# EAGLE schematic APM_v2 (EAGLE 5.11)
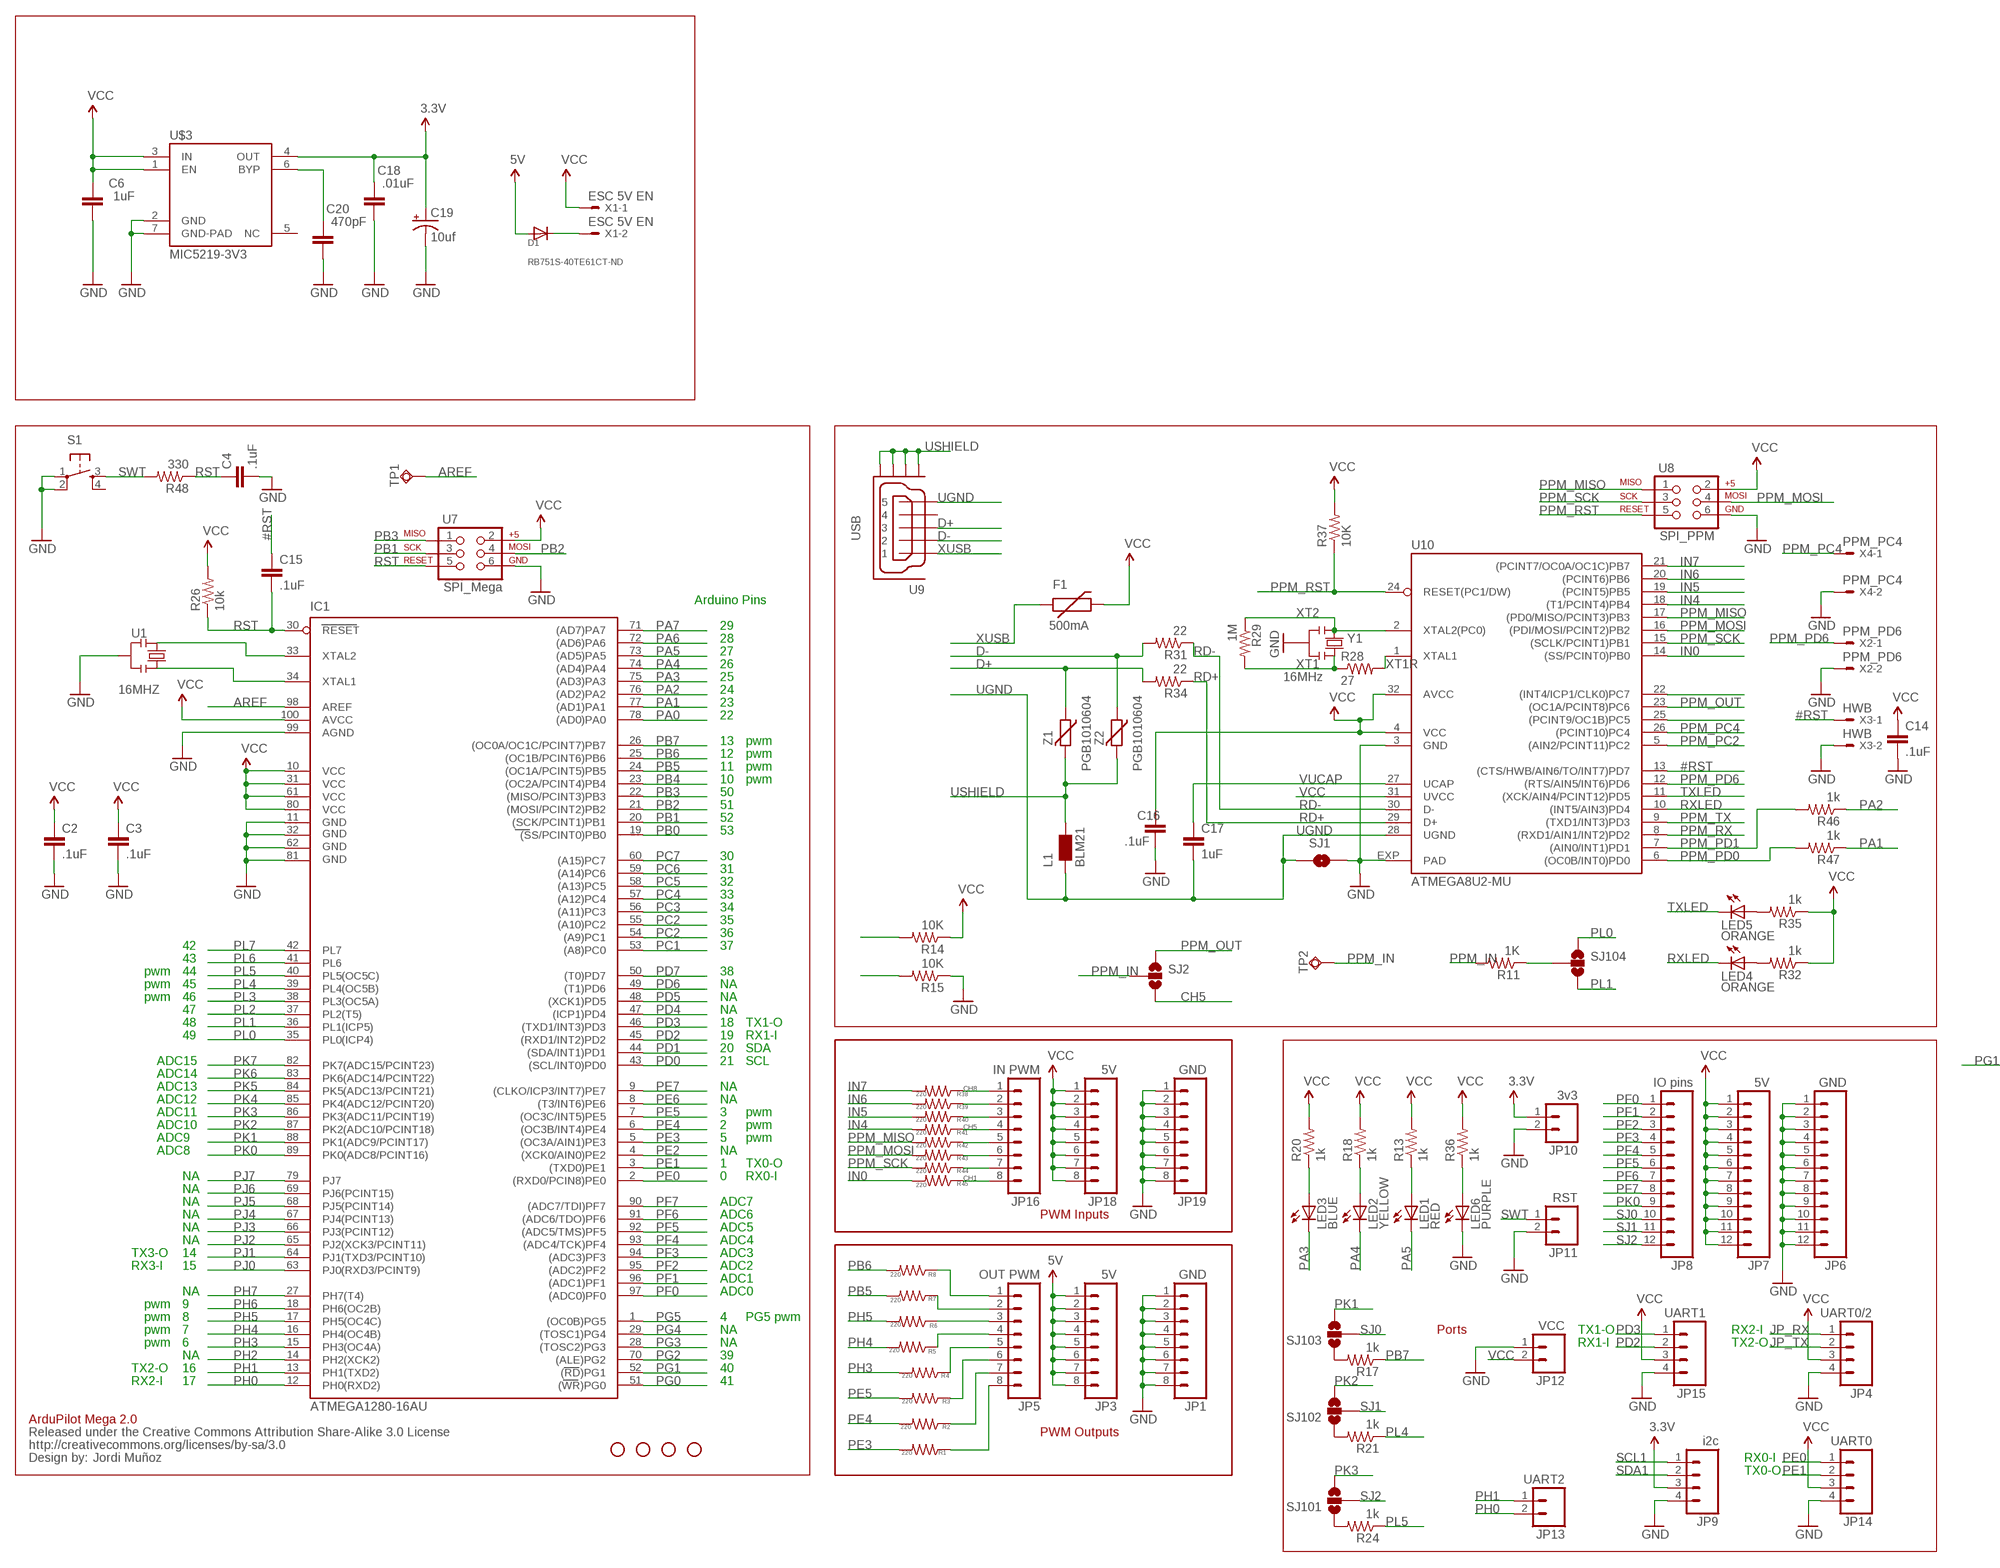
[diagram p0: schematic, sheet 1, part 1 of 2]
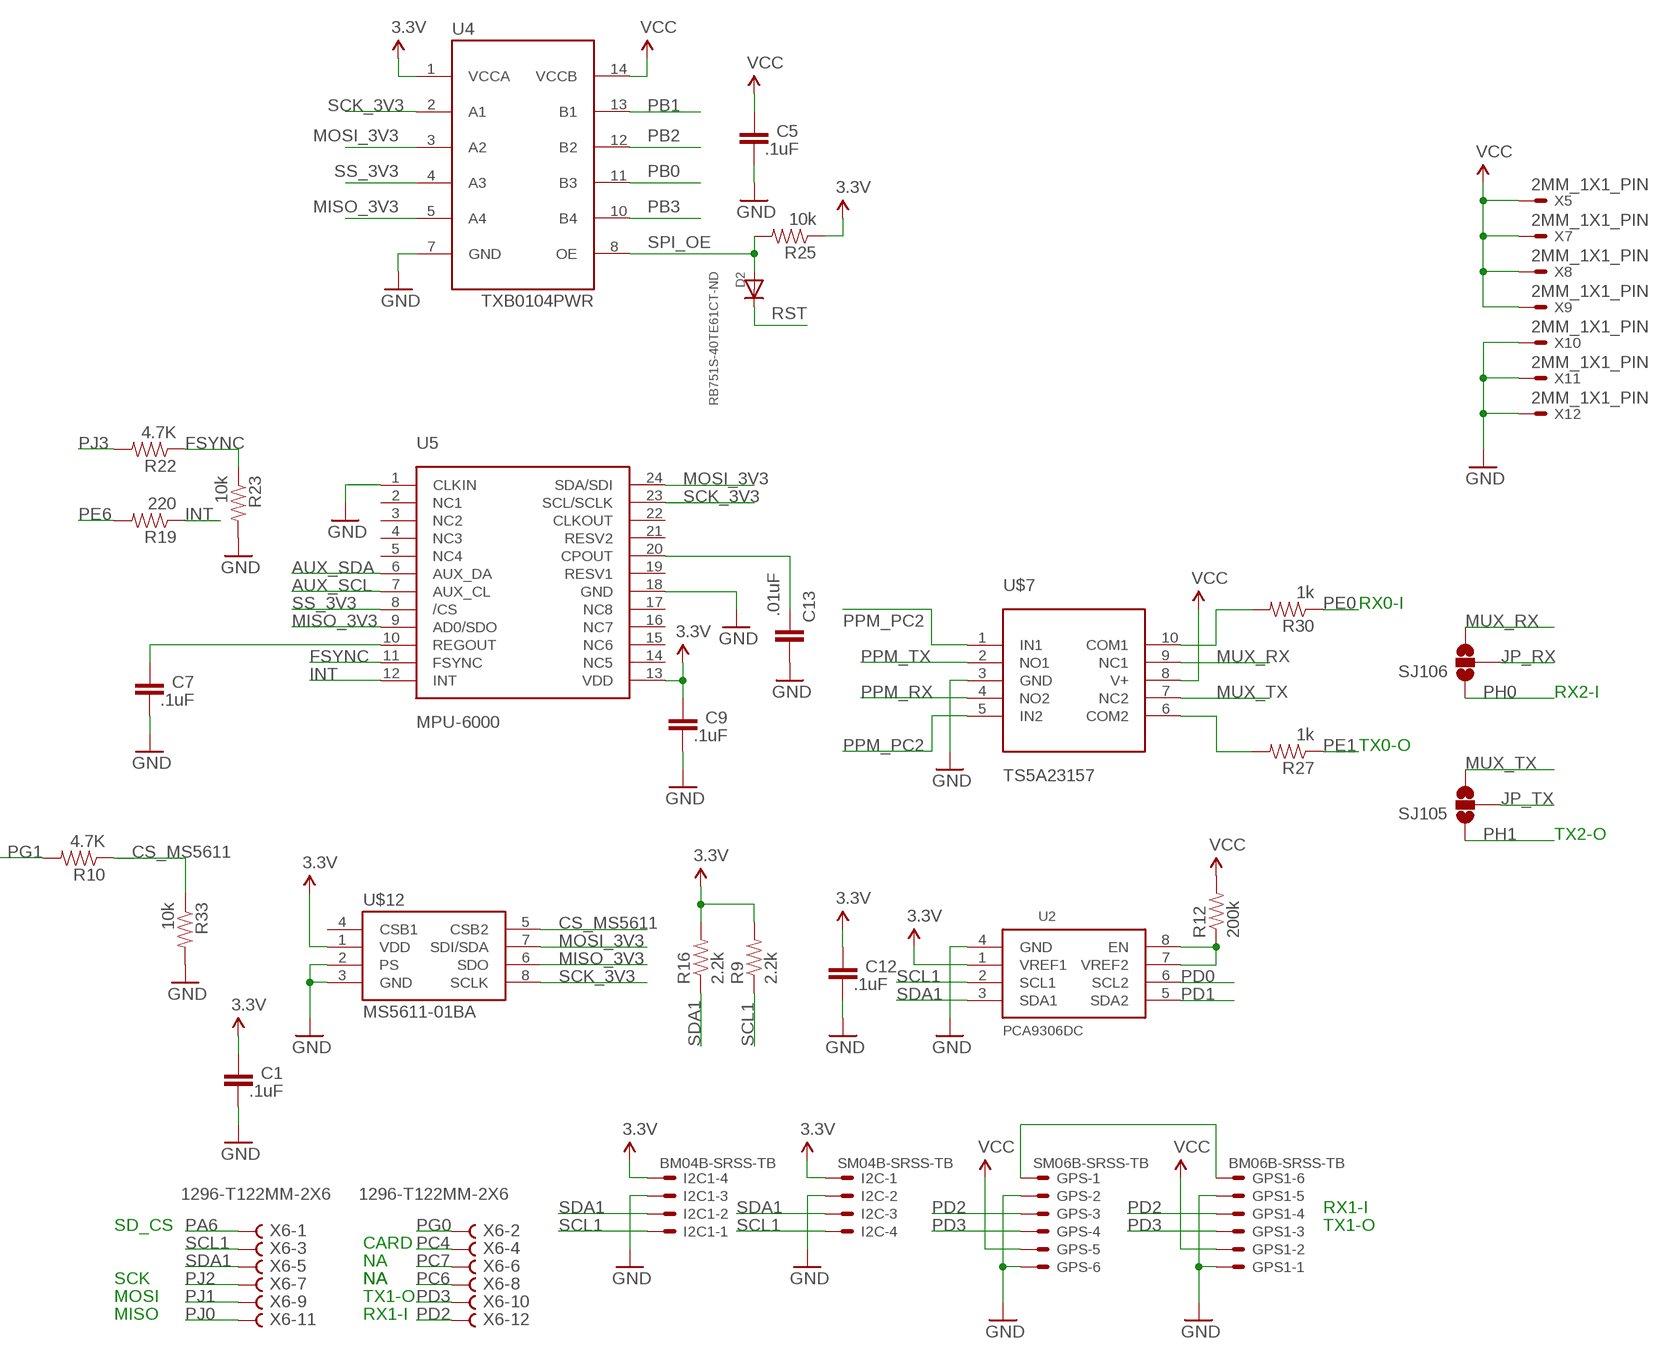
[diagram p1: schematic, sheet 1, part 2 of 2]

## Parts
C1  .1uF  C-EUC0402  [C0402]
C2  .1uF  CAP0402  [C0402]
C3  .1uF  CAP0402  [C0402]
C4  .1uF  CAP0402  [C0402]
C5  .1uF  C-EUC0402  [C0402]
C6  1uF  C-EUC0402  [C0402]
C7  .1uF  C-EUC0402  [C0402]
C9  .1uF  C-EUC0402  [C0402]
C12  .1uF  C-EUC0402  [C0402]
C13  .01uF  C-EUC0402  [C0402]
C14  .1uF  CAP0402  [C0402]
C15  .1uF  CAP0402  [C0402]
C16  .1uF  CAP0402-CAP  [0402-CAP]
C17  1uF  CAP0402-CAP  [0402-CAP]
C18  .01uF  C-EUC0402  [C0402]
C19  10uf  CAP_POL1206  [EIA3216]
C20  470pF  C-EUC0402  [C0402]
D1  RB751S-40TE61CT-ND  DIODESOD-123  [SOD-123]
D2  RB751S-40TE61CT-ND  DIODESOD-123  [SOD-123]
F1  500mA  PTCSMD  [PTC-1206]
GPS  SM06B-SRSS-TB  [SM06B-SRSS-TB]
GPS1  BM06B-SRSS-TB  [BM06B-SRSS-TB]
I2C  SM04B-SRSS-TB  [SM04B-SRSS-TB]
I2C1  BM04B-SRSS-TB  [BM04B-SRSS-TB]
IC1  ATMEGA1280-16AU  [TQFP100]
JP1  GND  M08  [1X08]
JP3  5V  M08  [1X08]
JP4  UART0/2  M04PTH  [1X04]
JP5  OUT PWM  M08  [1X08]
JP6  GND  M12PTH  [1X12]
JP7  5V  M12PTH  [1X12]
JP8  IO pins  M12PTH  [1X12]
JP9  i2c  M04PTH  [1X04]
JP10  3v3  M02PTH  [1X02]
JP11  RST  M02PTH  [1X02]
JP12  VCC  M02PTH  [1X02]
JP13  UART2  M02PTH  [1X02]
JP14  UART0  M04PTH  [1X04]
JP15  UART1  M04PTH  [1X04]
JP16  IN PWM  M08  [1X08]
JP18  5V  M08  [1X08]
JP19  GND  M08  [1X08]
L1  BLM21  WE-CBF_0805  [0805]
LED1  RED  LED0603  [LED-0603]
LED2  YELLOW  LED0603  [LED-0603]
LED3  BLUE  LED0603  [LED-0603]
LED4  ORANGE  LED0603  [LED-0603]
LED5  ORANGE  LED0603  [LED-0603]
LED6  PURPLE  LED0603  [LED-0603]
R1  220  RESISTOR0402  [C0402]
R2  220  RESISTOR0402  [C0402]
R3  220  RESISTOR0402  [C0402]
R4  220  RESISTOR0402  [C0402]
R5  220  RESISTOR0402  [C0402]
R6  220  RESISTOR0402  [C0402]
R7  220  RESISTOR0402  [C0402]
R8  220  RESISTOR0402  [C0402]
R9  2.2k  RESISTOR0402  [C0402]
R10  4.7K  RESISTOR0402  [C0402]
R11  1K  RESISTOR0402  [C0402]
R12  200k  RESISTOR0402  [C0402]
R13  1k  RESISTOR0402  [C0402]
R14  10K  RESISTOR0402-RES  [0402-RES]
R15  10K  RESISTOR0402-RES  [0402-RES]
R16  2.2k  RESISTOR0402  [C0402]
R17  1k  RESISTOR0402  [C0402]
R18  1k  RESISTOR0402  [C0402]
R19  220  RESISTOR0402  [C0402]
R20  1k  RESISTOR0402  [C0402]
R21  1k  RESISTOR0402  [C0402]
R22  4.7K  RESISTOR0402  [C0402]
R23  10k  RESISTOR0402  [C0402]
R24  1k  RESISTOR0402  [C0402]
R25  10k  RESISTOR0402  [C0402]
R26  10k  RESISTOR0402  [C0402]
R27  1k  RESISTOR0402-RES  [0402-RES]
R28  27  RESISTOR0402-RES  [0402-RES]
R29  1M  RESISTOR0402-RES  [0402-RES]
R30  1k  RESISTOR0402-RES  [0402-RES]
R31  22  RESISTOR0402-RES  [0402-RES]
R32  1k  RESISTOR0402-RES  [0402-RES]
R33  10k  RESISTOR0402  [C0402]
R34  22  RESISTOR0402-RES  [0402-RES]
R35  1k  RESISTOR0402-RES  [0402-RES]
R36  1k  RESISTOR0402  [C0402]
R37  10K  RESISTOR0402-RES  [0402-RES]
R38  220  RESISTOR0402  [C0402]
R39  220  RESISTOR0402  [C0402]
R40  220  RESISTOR0402  [C0402]
R41  220  RESISTOR0402  [C0402]
R42  220  RESISTOR0402  [C0402]
R43  220  RESISTOR0402  [C0402]
R44  220  RESISTOR0402  [C0402]
R45  220  RESISTOR0402  [C0402]
R46  1k  RESISTOR0402-RES  [0402-RES]
R47  1k  RESISTOR0402-RES  [0402-RES]
R48  330  RESISTOR0402  [C0402]
S1  TAC_SWITCHSMD  [TACTILE_SWITCH_SMD]
SJ1  SOLDERJUMPERTRACE  [SJ_2S-TRACE]
SJ2  SOLDERJUMPER_2WAYS  [SJ_3]
SJ101  SOLDERJUMPER_2WAYS  [SJ_3]
SJ102  SOLDERJUMPER_2WAYS  [SJ_3]
SJ103  SOLDERJUMPER_2WAYS  [SJ_3]
SJ104  SOLDERJUMPER_2WAYS  [SJ_3]
SJ105  SOLDERJUMPER_2WAYS  [SJ_3]
SJ106  SOLDERJUMPER_2WAYS  [SJ_3]
TP1  TPSQTP10SQ  [TP10SQ]
TP2  TPSQTP10SQ  [TP10SQ]
U1  16MHZ  RESONATORSMD  [RESONATOR-SMD]
U2  PCA9306DC  [VSSOP8]
U4  TXB0104PWR  [TSSOP14]
U5  MPU-6000  MPU-3000  [QFN-24]
U7  SPI_Mega  AVR_SPI_PRG_6NS  [2X3-NS]
U8  SPI_PPM  AVR_SPI_PRG_6NS  [2X3-NS]
U9  USB  MOLEX_MICRO_USB_AB_BOTTOM_MOUNT  [MOLEX_MICRO_USB_AB_BOTTOM_MOUNT]
U10  ATMEGA8U2-MU  [QFN32]
U$1  STAND-OFF  [STAND-OFF]
U$2  STAND-OFF  [STAND-OFF]
U$3  MIC5219-3V3  MIC5219  [MLF-6]
U$4  STAND-OFF  [STAND-OFF]
U$5  STAND-OFF  [STAND-OFF]
U$6  CREATIVE_COMMONS  [CREATIVE_COMMONS]
U$7  TS5A23157  [MSOP10]
U$12  MS5611-01BA  [MS5611-01BA]
X1  ESC 5V EN  87758-0216  [87758-0216]
X2  PPM_PD6  87758-0216  [87758-0216]
X3  HWB  87758-0216  [87758-0216]
X4  PPM_PC4  87758-0216  [87758-0216]
X5  2MM_1X1_PIN  [2MM_1X1_PIN]
X6  1296-T122MM-2X6  [2MM-DUAL-ROW-MALE-HEADER-SMT-2X6]
X7  2MM_1X1_PIN  [2MM_1X1_PIN]
X8  2MM_1X1_PIN  [2MM_1X1_PIN]
X9  2MM_1X1_PIN  [2MM_1X1_PIN]
X10  2MM_1X1_PIN  [2MM_1X1_PIN]
X11  2MM_1X1_PIN  [2MM_1X1_PIN]
X12  2MM_1X1_PIN  [2MM_1X1_PIN]
Y1  16MHz  RESONATORMU  [RESONATOR]
Z1  PGB1010604  VARISTORCN0603  [CT/CN0603]
Z2  PGB1010604  VARISTORCN0603  [CT/CN0603]

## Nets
3.3V: C1.2 C9.2 C12.2 C18.2 C19.A(+) I2C1.4 I2C.1 JP9.3 JP10.1 R9.2 R16.2 R25.1 U2.1(VREF1) U4.1(VCCA) U5.13(VDD) U$3.4(OUT) U$12.1(VDD)
5V: D1.A JP3.1 JP3.2 JP3.3 JP3.4 JP3.5 JP3.6 JP3.7 JP3.8
#RST: C15.1 U10.13((CTS/HWB/AIN6/TO/INT7)PD7) X3.1
AREF: IC1.98(AREF) TP1.TP
AUX_SCL: U5.7(AUX_CL)
AUX_SDA: U5.6(AUX_DA)
CH1: JP16.8 R45.1
CH5: JP16.4 R41.1 SJ2.3
CH8: JP16.1 R38.1
CS_MS5611: R10.1 R33.1 U$12.5(CSB2)
D+: R34.2 U9.3 Z1.1
D-: R31.2 U9.2 Z2.1
FSYNC: R22.1 R23.1 U5.11(FSYNC)
GND: C1.1 C2.2 C3.2 C4.2 C5.1 C6.1 C7.1 C9.1 C12.1 C13.1 C14.2 C16.2 C18.1 C19.C(-) C20.1 GPS1.1 GPS1.5 GPS.2 GPS.6 I2C1.3 I2C.2 IC1.11(GND) IC1.32(GND1) IC1.62(GND2) IC1.81(GND3) IC1.99(AGND) JP1.1 JP1.2 JP1.3 JP1.4 JP1.5 JP1.6 JP1.7 JP1.8 JP4.4 JP6.1 JP6.2 JP6.3 JP6.4 JP6.5 JP6.6 JP6.7 JP6.8 JP6.9 JP6.10 JP6.11 JP6.12 JP9.4 JP10.2 JP11.2 JP12.1 JP14.4 JP15.4 JP19.1 JP19.2 JP19.3 JP19.4 JP19.5 JP19.6 JP19.7 JP19.8 LED6.C R15.1 R23.2 R33.2 S1.1 S1.2 SJ1.2 U1.2 U2.4(GND) U4.7(GND) U5.1(CLKIN) U5.18(GND) U7.6 U8.6 U10.3(GND) U10.EXP(PAD) U$3.2(GND) U$3.7(GND-PAD) U$7.3(GND) U$12.2(PS) U$12.3(GND) X2.2 X3.2 X4.2 X10.P$1(S) X11.P$1(S) X12.P$1(S) Y1.2
HI: IC1.53((A8)PC0) IC1.54((A9)PC1) IC1.55((A10)PC2) IC1.56((A11)PC3) R14.2
IN0: R45.2 U10.14((SS/PCINT0)PB0)
IN4: R41.2 U10.18((T1/PCINT4)PB4)
IN5: R40.2 U10.19((PCINT5)PB5)
IN6: R39.2 U10.20((PCINT6)PB6)
IN7: R38.2 U10.21((PCINT7/OC0A/OC1C)PB7)
INT: R19.1 U5.12(INT)
JP_RX: JP4.1 SJ106.2
JP_TX: JP4.2 SJ105.2
LO: R15.2
MISO_3V3: U4.5(A4) U5.9(AD0/SDO) U$12.6(SDO)
MOSI_3V3: U4.3(A2) U5.24(SDA/SDI) U$12.7(SDI/SDA)
MUX_RX: SJ106.3 U$7.9(NC1)
MUX_TX: SJ105.3 U$7.7(NC2)
N$1: LED6.A R36.1
N$2: C13.2 U5.20(CPOUT)
N$3: C7.2 U5.10(REGOUT)
N$4: C20.2 U$3.6(BYP)
N$5: D1.C X1.2
N$6: U10.22((INT4/ICP1/CLK0)PC7)
N$8: JP5.5 R4.1
N$9: JP5.6 R3.1
N$10: JP5.7 R2.1
N$11: JP5.8 R1.1
N$12: R12.1 U2.7(VREF2) U2.8(EN)
N$13: JP5.4 R5.1
N$14: JP5.3 R6.1
N$15: JP5.2 R7.1
N$16: JP5.1 R8.1
N$19: JP16.2 R39.1
N$20: JP16.3 R40.1
N$22: JP16.5 R42.1
N$23: JP16.6 R43.1
N$24: JP16.7 R44.1
N$28: LED1.A R13.1
N$29: LED5.A R35.2
N$30: LED4.A R32.2
N$31: LED2.A R18.1
N$32: R30.2 U$7.10(COM1)
N$33: R27.2 U$7.6(COM2)
N$34: LED3.A R20.1
N$35: R11.1 SJ104.2
N$36: R17.2 SJ103.1
N$37: GPS1.6 GPS.1
N$38: R24.2 SJ101.1
N$39: R21.2 SJ102.1
N$56: IC1.34(XTAL1) U1.3
N$89: IC1.33(XTAL2) U1.1
PA0: IC1.78((AD0)PA0)
PA1: IC1.77((AD1)PA1) R47.1
PA2: IC1.76((AD2)PA2) R46.1
PA3: IC1.75((AD3)PA3) LED3.C
PA4: IC1.74((AD4)PA4) LED2.C
PA5: IC1.73((AD5)PA5) LED1.C
PA6: IC1.72((AD6)PA6) X6.1
PA7: IC1.71((AD7)PA7)
PB0: IC1.19((SS/PCINT0)PB0) U4.11(B3)
PB1: IC1.20((SCK/PCINT1)PB1) U4.13(B1) U7.3
PB2: IC1.21((MOSI/PCINT2)PB2) U4.12(B2) U7.4
PB3: IC1.22((MISO/PCINT3)PB3) U4.10(B4) U7.1
PB4: IC1.23((OC2A/PCINT4)PB4)
PB5: IC1.24((OC1A/PCINT5)PB5) R7.2
PB6: IC1.25((OC1B/PCINT6)PB6) R8.2
PB7: IC1.26((OC0A/OC1C/PCINT7)PB7) R17.1
PC4: IC1.57((A12)PC4) X6.4
PC5: IC1.58((A13)PC5)
PC6: IC1.59((A14)PC6) X6.8
PC7: IC1.60((A15)PC7) X6.6
PD0: IC1.43((SCL/INT0)PD0) U2.6(SCL2)
PD1: IC1.44((SDA/INT1)PD1) U2.5(SDA2)
PD2: GPS1.4 GPS.3 IC1.45((RXD1/INT2)PD2) JP15.2 X6.12
PD3: GPS1.3 GPS.4 IC1.46((TXD1/INT3)PD3) JP15.1 X6.10
PD4: IC1.47((ICP1)PD4)
PD5: IC1.48((XCK1)PD5)
PD6: IC1.49((T1)PD6)
PD7: IC1.50((T0)PD7)
PE0: IC1.2((RXD0/PCIN8)PE0) JP14.1 R30.1
PE1: IC1.3((TXD0)PE1) JP14.2 R27.1
PE2: IC1.4((XCK0/AIN0)PE2)
PE3: IC1.5((OC3A/AIN1)PE3) R1.2
PE4: IC1.6((OC3B/INT4)PE4) R2.2
PE5: IC1.7((OC3C/INT5)PE5) R3.2
PE6: IC1.8((T3/INT6)PE6) R19.2
PE7: IC1.9((CLKO/ICP3/INT7)PE7)
PF0: IC1.97((ADC0)PF0) JP8.1
PF1: IC1.96((ADC1)PF1) JP8.2
PF2: IC1.95((ADC2)PF2) JP8.3
PF3: IC1.94((ADC3)PF3) JP8.4
PF4: IC1.93((ADC4/TCK)PF4) JP8.5
PF5: IC1.92((ADC5/TMS)PF5) JP8.6
PF6: IC1.91((ADC6/TDO)PF6) JP8.7
PF7: IC1.90((ADC7/TDI)PF7) JP8.8
PG0: IC1.51((WR)PG0) X6.2
PG1: IC1.52((RD)PG1) R10.2
PG2: IC1.70((ALE)PG2)
PG3: IC1.28((TOSC2)PG3)
PG4: IC1.29((TOSC1)PG4)
PG5: IC1.1((OC0B)PG5)
PH0: IC1.12(PH0(RXD2)) JP13.2 SJ106.1
PH1: IC1.13(PH1(TXD2)) JP13.1 SJ105.1
PH2: IC1.14(PH2(XCK2))
PH3: IC1.15(PH3(OC4A)) R4.2
PH4: IC1.16(PH4(OC4B)) R5.2
PH5: IC1.17(PH5(OC4C)) R6.2
PH6: IC1.18(PH6(OC2B))
PH7: IC1.27(PH7(T4))
PJ0: IC1.63(PJ0(RXD3/PCINT9)) X6.11
PJ1: IC1.64(PJ1(TXD3/PCINT10)) X6.9
PJ2: IC1.65(PJ2(XCK3/PCINT11)) X6.7
PJ3: IC1.66(PJ3(PCINT12)) R22.2
PJ4: IC1.67(PJ4(PCINT13))
PJ5: IC1.68(PJ5(PCINT14))
PJ6: IC1.69(PJ6(PCINT15))
PJ7: IC1.79(PJ7)
PK0: IC1.89(PK0(ADC8/PCINT16)) JP8.9
PK1: IC1.88(PK1(ADC9/PCINT17)) SJ103.3
PK2: IC1.87(PK2(ADC10/PCINT18)) SJ102.3
PK3: IC1.86(PK3(ADC11/PCINT19)) SJ101.3
PK4: IC1.85(PK4(ADC12/PCINT20))
PK5: IC1.84(PK5(ADC13/PCINT21))
PK6: IC1.83(PK6(ADC14/PCINT22))
PK7: IC1.82(PK7(ADC15/PCINT23))
PL0: IC1.35(PL0(ICP4)) SJ104.1
PL1: IC1.36(PL1(ICP5)) SJ104.3
PL2: IC1.37(PL2(T5))
PL3: IC1.38(PL3(OC5A))
PL4: IC1.39(PL4(OC5B)) R21.1
PL5: IC1.40(PL5(OC5C)) R24.1
PL6: IC1.41(PL6)
PL7: IC1.42(PL7)
PPM_IN: R11.2 SJ2.2 TP2.TP
PPM_MISO: R42.2 U8.1 U10.17((PD0/MISO/PCINT3)PB3)
PPM_MOSI: R43.2 U8.4 U10.16((PDI/MOSI/PCINT2)PB2)
PPM_OUT: SJ2.1 U10.23((OC1A/PCINT8)PC6)
PPM_PC2: U10.5((AIN2/PCINT11)PC2) U$7.1(IN1) U$7.5(IN2)
PPM_PC4: U10.26((PCINT10)PC4) X4.1
PPM_PD0: R47.2 U10.6((OC0B/INT0)PD0)
PPM_PD1: R46.2 U10.7((AIN0/INT1)PD1)
PPM_PD6: U10.12((RTS/AIN5/INT6)PD6) X2.1
PPM_RST: R37.1 U8.5 U10.24(RESET(PC1/DW))
PPM_RX: U10.8((RXD1/AIN1/INT2)PD2) U$7.4(NO2)
PPM_SCK: R44.2 U8.3 U10.15((SCLK/PCINT1)PB1)
PPM_TX: U10.9((TXD1/INT3)PD3) U$7.2(NO1)
RD+: R34.1 U10.29(D+)
RD-: R31.1 U10.30(D-)
RST: C4.1 C15.2 D2.C IC1.30(RESET) R26.1 R48.1 U7.5
RXLED: LED4.C U10.10((INT5/AIN3)PD4)
SCK_3V3: U4.2(A1) U5.23(SCL/SCLK) U$12.8(SCLK)
SCL1: I2C1.1 I2C.4 JP9.1 R9.1 U2.2(SCL1) X6.3
SDA1: I2C1.2 I2C.3 JP9.2 R16.1 U2.3(SDA1) X6.5
SJ0: JP8.10 SJ103.2
SJ1: JP8.11 SJ102.2
SJ2: JP8.12 SJ101.2
SPI_OE: D2.A R25.2 U4.8(OE)
SS_3V3: U4.4(A3) U5.8(/CS)
SWT: JP11.1 R48.2 S1.3
TXLED: LED5.C U10.11((XCK/AIN4/PCINT12)PD5)
UGND: C17.2 L1.1 SJ1.1 U9.5 U10.28(UGND)
USHIELD: L1.2 U9.GND1 U9.GND2 U9.GND3 U9.GND4 Z1.2 Z2.2
VCC: C2.1 C3.1 C5.2 C6.2 C14.1 C16.1 F1.2 GPS1.2 GPS.5 IC1.10(VCC) IC1.31(VCC1) IC1.61(VCC2) IC1.80(VCC3) IC1.100(AVCC) JP4.3 JP7.1 JP7.2 JP7.3 JP7.4 JP7.5 JP7.6 JP7.7 JP7.8 JP7.9 JP7.10 JP7.11 JP7.12 JP12.2 JP14.3 JP15.3 JP18.1 JP18.2 JP18.3 JP18.4 JP18.5 JP18.6 JP18.7 JP18.8 R12.2 R13.2 R14.1 R18.2 R20.2 R26.2 R32.1 R35.1 R36.2 R37.2 U4.14(VCCB) U7.2 U8.2 U10.4(VCC) U10.25((PCINT9/OC1B)PC5) U10.31(UVCC) U10.32(AVCC) U$3.1(EN) U$3.3(IN) U$7.8(V+) X1.1 X5.P$1(S) X7.P$1(S) X8.P$1(S) X9.P$1(S)
VUCAP: C17.1 U10.27(UCAP)
XT1: R28.1 R29.2 Y1.3
XT1R: R28.2 U10.1(XTAL1)
XT2: R29.1 U10.2(XTAL2(PC0)) Y1.1
XUSB: F1.1 U9.1
Unconnected: S1.4 U5.2(NC1) U5.3(NC2) U5.4(NC3) U5.5(NC4) U5.14(NC5) U5.15(NC6) U5.16(NC7) U5.17(NC8) U5.19(RESV1) U5.21(RESV2) U5.22(CLKOUT) U9.4 U$3.5(NC) U$12.4(CSB1)

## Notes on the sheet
- Arduino Pins
- 29
- 28
- 27
- 26
- 25
- 24
- 23
- 22
- 13 | pwm
- 12 | pwm
- 11 | pwm
- 10 | pwm
- 50
- 51
- 52
- 53
- 30
- 31
- 32 | RX0-I
- 33
- PC3 | 34
- PC2 | 35
- PC2 | 36
- 42 | PC1 | 37 | RX2-I
- 43
- pwm | 44 | 38
- pwm | 45 | NA | TX0-O
- pwm | 46 | NA
- 47 | NA
- 48 | 18 | TX1-O
- 49 | 19 | RX1-I
- 20 | SDA | TX2-O
- ADC15 | 21 | SCL
- ADC14
- ADC13 | NA
- ADC12 | NA
- ADC11 | 3 | pwm
- ADC10 | 2 | pwm
- ADC9 | 5 | pwm
- ADC8 | NA
- 1 | TX0-O
- NA | 0 | RX0-I
- NA
- NA | ADC7
- NA | ADC6 | PWM Inputs
- NA | ADC5
- NA | ADC4
- TX3-O | 14 | ADC3
- RX3-I | 15 | ADC2
- ADC1
- NA | ADC0
- pwm | 9
- pwm | 8 | 4 | PG5 pwm | RX1-I
- pwm | 7 | NA | Ports | TX1-O | RX2-I | SD_CS | TX1-O
- pwm | 6 | NA | RX1-I | TX2-O | CARD
- NA | 39 | NA
- TX2-O | 16 | 40 | SCK | NA | NA
- RX2-I | 17 | 41 | MOSI | TX1-O
- MISO | RX1-I
- ArduPilot Mega 2.0
- PWM Outputs
- Jordi Muñoz | RX0-I
- TX0-O

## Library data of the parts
C1 C5-C7 C9 C12 C13 C18 C20 = SmartPrj:C-EU: CAPACITOR, European symbol
C2-C4 C14 C15 = DIYdrones3:CAP: Capacitor
C16 C17 = SparkFun:CAP: Capacitor
C19 = SparkFun:CAP_POL: Capacitor Polarized
D1 D2 = adafruit:DIODE: Diode
F1 = SparkFun:PTC: Resettable Fuse PTC
GPS GPS1 = con-jst2:?M06B-SRSS-TB: Disconnectable Crimp style connector, 1.0mm pitch 6 contacts
I2C I2C1 = con-jst2:?M04B-SRSS-TB: Disconnectable Crimp style connector, 1.0mm pitch 4 contacts
IC1 = atmel-2010:ATMEGA*: MICROCONTROLLER 64/128/256 Kbytes FLASH 4 Kbytes EEPROM 8 Kbytes SRAM 86 General Purpose I/O pins 12-channels16-bit PWM 4 x Serial USARTs 16-channels 10-bit A/D
JP1 JP3 JP5 JP16 JP18 JP19 = SparkFunv2:M08: Header 8 Standard 8-pin 0.1" header. Use with straight break away headers (SKU : PRT-00116), right angle break away headers (PRT-00553), swiss pins (PRT-00743), machine pins (PRT-00117), and female headers (PRT-00115).
JP4 JP9 JP14 JP15 = SparkFun:M04: Header 4 Standard 4-pin 0.1" header. Use with straight break away headers (SKU : PRT-00116), right angle break away headers (PRT-00553), swiss pins (PRT-00743), machine pins (PRT-00117), and female headers (PRT-00115). Molex polarized connector foot print use with SKU : PRT-08231 with associated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
JP6-JP8 = SparkFun:M12: Header 12 Standard 12-pin 0.1" header. Use with straight break away headers (SKU : PRT-00116), right angle break away headers (PRT-00553), swiss pins (PRT-00743), machine pins (PRT-00117), and female headers (PRT-00115).
JP10-JP13 = SparkFun:M02: Header 2
L1 = wuerth-elektronik:WE-CBF: SMD EMI Suppression Ferrite Beads
LED1-LED3 LED6 = DIYdrones3:LED: LEDs
LED4 LED5 = SparkFun:LED: LEDs
R1-R13 R16-R26 R33 R36 R38-R45 R48 = DIYdrones3:RESISTOR: Resistor
R14 R15 R27-R32 R34 R35 R37 R46 R47 = SparkFun:RESISTOR: Resistor
S1 = DIYdrones3:TAC_SWITCH: Momentary Switch Button commonly used for reset or general input. Spark Fun Electronics SKU : COM-00097
SJ1 = SparkFun:SOLDERJUMPER: Solder Jumper
SJ2 SJ101-SJ106 = SparkFun:SOLDERJUMPER_2WAY: Solder Jumper 2 way solder jumper
TP1 TP2 = testpad:TPSQ: Test pad
U1 = DIYdrones3:RESONATOR: Resonator Small SMD resonator. This is the itty bitty 10/20MHz resonators with built in caps. CSTCE10M0G55 and CSTCE20M0V53. Footprint has been reviewed closely but hasn't been tested yet.
U2 = DIYdrones_082610:PCA9306DC
U4 = bibaja:TXB0104: 4-bit Bidirectional Voltage-Level Translator
U5 = 3DRobotics_Master_Library:MPU-3000: Invensense MPU-3000 Motion Processing Unit The MPU-30X0 Motion Processing Unit (MPU?) is the world?s first motion processing solution with integrated 6-axis sensor fusion for smart phone applications. The MPU-30X0 has an embedded 3- axis gyroscope and Digital Motion Processor? (DMP) hardware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; DATASHEET: http://invensense.com/mems/gyro/documents/PS-MPU-3000A-00_v2.6.pdf; LINK: http://www.invensense.com/mems/gyro/mpu3000.html; MFGPN: MPU-3000
U7 U8 = SparkFunv2:AVR_SPI_PRG_6: AVR ISP 6 Pin This is the reduced ISP connector for AVR programming. Common on Arduino. This footprint will take up less PCB space and can be used with a 10-pin to 6-pin adapter such as SKU: BOB-08508
U9 = 3DRobotics:MOLEX_MICRO_USB_AB_BOTTOM_MOUNT: Molex Micro USB AB Bottom Mount Receptacle; DATASHEET: http://www.molex.com/pdm_docs/sd/475890001_sd.pdf; LINK: http://www.molex.com/molex/products/datasheet.jsp?part=active/0475890001_IO_CONNECTORS.xml&channel=Products&Lang=en-US; MFGPN: 47589-0001
U10 = atmel:ATMEGA8U2-MU
U$1 U$2 U$4 U$5 = DIYdrones3:STAND-OFF: Stand Off
U$3 = 3DRobotics:MIC5219: Micrel MIC5219 500mA peak output LDO regulator The MIC5219 is an efficient linear voltage regulator with high peak output current capability, very-low-dropout voltage, and better than 1% output voltage accuracy. Dropout is typically 10mV at light loads and less than 500mV at full load. The MIC5219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; DATASHEET: http://www.micrel.com/_PDF/mic5219.pdf; LINK: http://www.micrel.com/page.do?page=/product-info/products/mic5219.shtml; MFGPN: MIC5219
U$6 = SparkFun:CREATIVE_COMMONS
U$7 = 3DRobotics:TS5A23157: TS5A23157 Dual 10-Ohm SPDT Analog Switch The TS5A23157 is a dual single-pole double-throw (SPDT) analog switch designed to operate from 1.65 V to 5.5 V. This device can handle both digital and analog signals. Signals up to 5.5 V (peak) can be transmitted in either direction.; DATASHEET: http://focus.ti.com/lit/ds/symlink/ts5a23157.pdf; LINK: http://focus.ti.com/docs/prod/folders/print/ts5a23157.html; MFGPN: TS5A23157DGSR
U$12 = 3DRobotics:MS5611-01BA: MS5611-01BA The MS5611-01BA is a new generation of high resolution altimeter sensors from MEAS Switzerland with SPI and I 2 C bus interface. It is optimized for altimeters and variometers with an altitude resolution of 10 cm. The sensor module includes a high linearity pressure sensor and an ultra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; DATASHEET: http://www.meas-spec.com/downloads/MS5611-01BA01.pdf; LINK: http://www.meas-spec.com/product/t_product.aspx?id=8503#; MFGPN: MS5611-01BA
X1-X4 = con-molex:87758-0216: 2 Pin - 2mm Dual Row Single Wafer, Vertical T/H HDR; MPN: 87758-0216; OC_FARNELL: unknown; OC_NEWARK: 94M1513
X5 X7-X12 = 3DRobotics:2MM_1X1_PIN: 2 Pin - 2mm Dual Row Single Wafer, Vertical T/H HDR
X6 = 3DRobotics:1296-T12: 1.27mm SINGLE ROW FEMALE SOCKET Source: http://www.leotronics.co.uk/Conexcon/Data%20Sheets/sec.%20A/1296ing.pdf
Y1 = SmartPrj:RESONATOR
Z1 Z2 = varistor:VARISTOR: VARISTOR

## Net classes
0 default: width 0.178 mm, drill 0.381 mm, clearance 0.178 mm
